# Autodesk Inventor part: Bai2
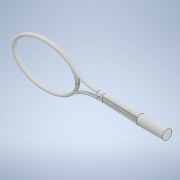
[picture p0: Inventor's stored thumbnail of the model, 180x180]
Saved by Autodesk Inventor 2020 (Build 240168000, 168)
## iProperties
Created: 2021-04
Part Number: Bai2
Material: Generic
Document SubType Name: Modeling
Designer: Hao
Density: 1 g/cm^3
Appearance: Default
Author: Hao
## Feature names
1. Sweep1
2. Sweep2
3. Mirror1
4. Extrusion1
5. Extrusion2
## Parameters: d4 = 12.5 mm, d7 = 7 mm, d9 = 0, d10 = 0, d11 = 8.75 mm, d12 = 5 mm, d13 = 8.75 mm, d14 = 5 mm, d15 = 0, d16 = 0, d18 = 175 mm, d22 = 175 mm, d23 = 1.5 deg, d24 = 45 mm, d25 = 125 mm, d26 = 0
